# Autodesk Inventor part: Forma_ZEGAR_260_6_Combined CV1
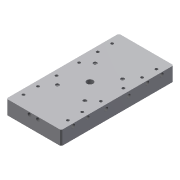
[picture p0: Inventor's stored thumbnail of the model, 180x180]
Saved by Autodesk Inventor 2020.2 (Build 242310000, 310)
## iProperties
Created: 2015-01
Part Number: Forma_ZEGAR_260_6_Combined CV1
Material: Ogólny
Document SubType Name: Modeling
Designer: F.Stasiak
Density: 1 g/cm^3
Appearance: Domyślna
Mass: 1418.12 g
Surface Area: 2056.51 cm^2
Volume: 1418.12 cm^3
Catalog Web Link: www.expertbooks.pl
Manager: www.cadconsulting.pl
Company: Fabian Stasiak CAD Consulting
Author: F.Stasiak
Subject: Zbiór ćwiczeń. Autodesk Inventor 2020. Kurs Professional
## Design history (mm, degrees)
node "Forma_ZEGAR_260_4_AsmContainer" dims "d0" = 10
sketch "Szkic1"
  geometry: L1 (-78, 160)-(78, 160) reference; L2 (78, 160)-(78, -160) reference; L3 (78, -160)-(-78, -160) reference; L4 (-78, -160)-(-78, 160) reference; L5 (-78, 160)-(78, 160) reference; L6 (78, 160)-(78, -160) reference; L7 (78, -160)-(-78, -160) reference; L8 (-78, -160)-(-78, 160) reference; L9 (-78, 160)-(78, 160) reference; L10 (78, 160)-(78, -160) reference; L11 (78, -160)-(-78, -160) reference; L12 (-78, -160)-(-78, 160) reference; L13 (-78, 160)-(78, 160) reference; L14 (78, 160)-(78, -160) reference; L15 (78, -160)-(-78, -160) reference; L16 (-78, -160)-(-78, 160) reference; L17 (-78, 160)-(78, 160); L18 (78, 160)-(78, -160); L19 (78, -160)-(-78, -160); L20 (-78, -160)-(-78, 160)
  constraints: 8 end point, 2 parallel, 1 horizontal, 1 perpendicular
sketch "Szkic2"
  geometry: L1 (-78, 160)-(78, 160) reference; L2 (78, 160)-(78, -160) reference; L3 (78, -160)-(-78, -160) reference; L4 (-78, -160)-(-78, 160) reference
sketch "Szkic3"
  geometry: L1 (-78, 160)-(78, 160) reference; L2 (78, 160)-(78, -160) reference; L3 (78, -160)-(-78, -160) reference; L4 (-78, -160)-(-78, 160) reference
sketch "Szkic4"
  geometry: L1 (-78, 160)-(78, 160) reference; L2 (78, 160)-(78, -160) reference; L3 (78, -160)-(-78, -160) reference; L4 (-78, -160)-(-78, 160) reference
sketch "Szkic5"
  geometry: L1 (-78, 160)-(78, 160) reference; L2 (78, 160)-(78, -160) reference; L3 (78, -160)-(-78, -160) reference; L4 (-78, -160)-(-78, 160) reference
chamfer "Faza1" distance "d1" = 3; stored, may be unused: second distance "d2" = 3, angle "d3" = 45 deg
chamfer "Faza2" distance "d4" = 3; stored, may be unused: second distance "d5" = 3, angle "d6" = 45 deg
chamfer "Faza3" distance "d7" = 3; stored, may be unused: second distance "d8" = 3, angle "d9" = 45 deg
chamfer "Faza4" distance "d10" = 3; stored, may be unused: second distance "d11" = 3, angle "d12" = 45 deg
feature "Rzeźbienie2"
feature "Gwint1" dims "d13" = 0, "d14" = 0
feature "Rzeźbienie3"
feature "Gwint2" dims "d15" = 0, "d16" = 0
feature "Rzeźbienie4"
feature "Rzeźbienie5"
feature "Gwint3" dims "d17" = 0, "d18" = 0
feature "Rzeźbienie6"
feature "Gwint4" dims "d19" = 0, "d20" = 0
feature "Rzeźbienie7"
feature "Rzeźbienie8"
feature "Gwint5" dims "d21" = 0, "d22" = 0
feature "Rzeźbienie9"
feature "Gwint6" dims "d23" = 0, "d24" = 0
feature "Rzeźbienie10"
feature "Gwint7" dims "d25" = 0, "d26" = 0
feature "Rzeźbienie11"
feature "Gwint8" dims "d27" = 0, "d28" = 0
feature "Rzeźbienie12"
feature "Rzeźbienie13"
feature "Rzeźbienie27"
feature "Rzeźbienie28"
node "Bryła1"
node "Forma_ZEGAR_260_4_ZEGAR_260_CV_1:1" dims "d0" = 10
node "Forma_ZEGAR_260_4_ZEGAR_260_CV_2:1" dims "d0" = 10
node "Forma_ZEGAR_260_4_ZEGAR_260_CV_3:1" dims "d0" = 10
node "Forma_ZEGAR_260_4_ZEGAR_260_CV_4:1" dims "d0" = 10
feature "Powierzchnia2"
body "Srf2"
feature "Powierzchnia3"
body "Srf3"
feature "Powierzchnia4"
body "Srf4"
feature "Powierzchnia5"
body "Srf5"
feature "Powierzchnia6"
body "Srf6"
feature "Powierzchnia7"
body "Srf7"
feature "Powierzchnia8"
body "Srf8"
feature "Powierzchnia9"
body "Srf9"
feature "Powierzchnia10"
body "Srf10"
feature "Powierzchnia11"
body "Srf11"
feature "Powierzchnia12"
body "Srf12"
feature "Powierzchnia13"
body "Srf13"
feature "Powierzchnia27"
body "Srf27"
feature "Powierzchnia28"
body "Srf28"
